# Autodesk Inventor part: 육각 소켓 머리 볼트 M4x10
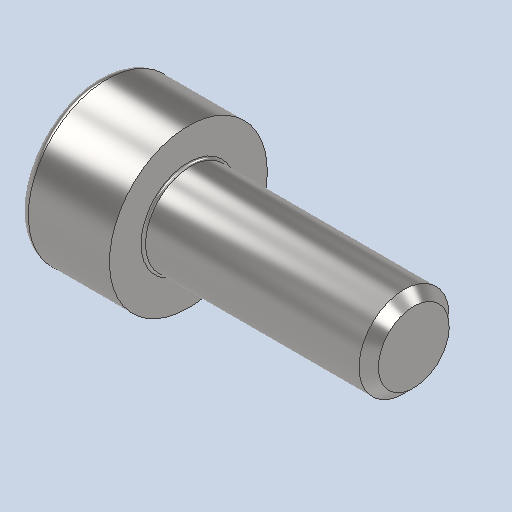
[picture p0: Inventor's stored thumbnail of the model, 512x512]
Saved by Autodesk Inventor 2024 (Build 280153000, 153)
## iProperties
Created: 2024-10
Part Number: 육각 소켓 머리 볼트 M4x10
Material: 강철, 연강
Description: 6각머리 태핑 나사
Document SubType Name: Modeling
Designer: user
Density: 7.85 g/cm^3
Appearance: 기본값
Author: jhkim
Sending System: Autodesk Inventor 2025
Preprocessor: ST-DEVELOPER v20
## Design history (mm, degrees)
feature "Solid1"
node "솔리드1"
